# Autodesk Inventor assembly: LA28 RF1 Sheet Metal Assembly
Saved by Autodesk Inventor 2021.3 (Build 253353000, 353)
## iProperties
Created: 2023-01
Part Number: LA28 RF1 Sheet Metal Assembly
Document SubType Name: Assembly
Designer: AdminForWorker
Title: LA28 RF1 Sheet Metal Assembly v3
Author: AdminForWorker
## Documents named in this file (8)
- c:\worker\convert-fusion-r08-cosv3\tmp\job-1\5\output\files\a86acfbb-7093-441b-87ec-5aa5153615de\LA28 RF1 Sheet Metal Assembly v3.iam
- c:\worker\convert-fusion-r08-cosv3\tmp\job-1\5\output\files\a86acfbb-7093-441b-87ec-5aa5153615de\LA28RF1 Front Rear C Channel^la28RF1 SHEET METAL ASSEMBLY.ipt
- c:\worker\convert-fusion-r08-cosv3\tmp\job-1\5\output\files\a86acfbb-7093-441b-87ec-5aa5153615de\LA28RF1 Center Bar^la28RF1 SHEET METAL ASSEMBLY.ipt
- c:\worker\convert-fusion-r08-cosv3\tmp\job-1\5\output\files\a86acfbb-7093-441b-87ec-5aa5153615de\AL28RF1 Outer Bar^la28RF1 SHEET METAL ASSEMBLY.ipt
- c:\worker\convert-fusion-r08-cosv3\tmp\job-1\5\output\files\a86acfbb-7093-441b-87ec-5aa5153615de\Inclinometer Mount Plate^la28RF1 SHEET METAL ASSEMBLY.ipt
- c:\worker\convert-fusion-r08-cosv3\tmp\job-1\5\output\files\a86acfbb-7093-441b-87ec-5aa5153615de\Stabilizing Tube^la28RF1 SHEET METAL ASSEMBLY.ipt
- c:\worker\convert-fusion-r08-cosv3\tmp\job-1\5\output\files\a86acfbb-7093-441b-87ec-5aa5153615de\Rear Connection Arm^la28RF1 SHEET METAL ASSEMBLY.ipt
- c:\worker\convert-fusion-r08-cosv3\tmp\job-1\5\output\files\a86acfbb-7093-441b-87ec-5aa5153615de\LA18 LA28 Front Connection Tongue^la28RF1 SHEET METAL ASSEMBLY.ipt
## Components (15 placed, 7 different names)
1. LA28RF1 Front Rear C Channel^la28RF1 SHEET METAL ASSEMBLY:1
2. LA28RF1 Front Rear C Channel^la28RF1 SHEET METAL ASSEMBLY:2
3. LA28RF1 Center Bar^la28RF1 SHEET METAL ASSEMBLY:1
4. LA28RF1 Center Bar^la28RF1 SHEET METAL ASSEMBLY:2
5. AL28RF1 Outer Bar^la28RF1 SHEET METAL ASSEMBLY:1
6. AL28RF1 Outer Bar^la28RF1 SHEET METAL ASSEMBLY:2
7. AL28RF1 Outer Bar^la28RF1 SHEET METAL ASSEMBLY:3
8. AL28RF1 Outer Bar^la28RF1 SHEET METAL ASSEMBLY:4
9. Inclinometer Mount Plate^la28RF1 SHEET METAL ASSEMBLY:1
10. Stabilizing Tube^la28RF1 SHEET METAL ASSEMBLY:1
11. Stabilizing Tube^la28RF1 SHEET METAL ASSEMBLY:2
12. Rear Connection Arm^la28RF1 SHEET METAL ASSEMBLY:1
13. Rear Connection Arm^la28RF1 SHEET METAL ASSEMBLY:2
14. LA18 LA28 Front Connection Tongue^la28RF1 SHEET METAL ASSEMBLY:1
15. LA18 LA28 Front Connection Tongue^la28RF1 SHEET METAL ASSEMBLY:2
